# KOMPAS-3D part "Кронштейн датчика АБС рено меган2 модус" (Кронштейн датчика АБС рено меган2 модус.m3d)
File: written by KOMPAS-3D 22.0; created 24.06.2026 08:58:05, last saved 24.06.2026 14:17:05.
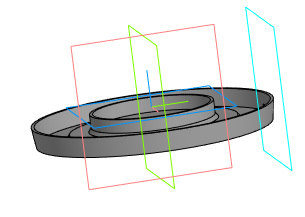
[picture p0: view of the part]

Document properties: Автор: 1; Полное имя файла: J:\3D модели\Кронштейн датчика АБС рено меган2 модус.m3d

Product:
- Part/product: Кронштейн датчика АБС рено меган2 модус
    Масса: 0.049745

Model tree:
1. Эскиз:1
2. Элемент вращения:1
     Угол 1 = 360
3. Смещенная плоскость:1
     Расстояние = 41
4. Эскиз:2
5. Элемент выдавливания:2
     Расстояние 2 = 8.8

Expressions: 20*m; 5*m; m*43/2; m*56/2; m*59/2; m*80/2; m*7; m*9; m*41; 1*m; 12*m; 2*m; 8.8*m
